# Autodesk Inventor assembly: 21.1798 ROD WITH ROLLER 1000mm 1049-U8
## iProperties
Created: 2007-03
Part Number: 21.1798 ROD WITH ROLLER 1000mm 1049-U8
Document SubType Name: Assembly
Designer: Andy Moles
Translation Standard: STEP AP214IS
File Name: 1049-U8_ASM
Preprocessor: PRO/ENGINEER BY PARAMETRIC TECHNOLOGY CORPORATION, 2005310
Postprocessor: Build: 344b, Release: 11 SP2 - Date: Fri 08/18/2006
Sent Units: MILLIMETERS
Uncertainty: 0.10980916782030001
Author: Andy Moles
